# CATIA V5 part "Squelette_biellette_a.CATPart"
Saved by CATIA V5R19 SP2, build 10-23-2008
Part number: squelette_biellette_a
Bounding box of the stored display mesh (mm): x -23 to -23, y -294 to -294, z -144 to 80
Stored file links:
  G:\EU_thinkMotion\CFAO_2010\MMS_groupe3\MMS_groupe3\pmayet\pmayet_assemblage_animation\pmayet_assemblage_animation\Squelette_biellette_a.CATPart
  G:\EU_thinkMotion\CFAO_2010\MMS_groupe3\MMS_groupe3\pmayet\pmayet_assemblage_animation\pmayet_assemblage_animation\pmayet_assemblage_animation.CATProduct
  G:\EU_thinkMotion\CFAO_2010\MMS_groupe3\MMS_groupe3\pmayet\pmayet_assemblage_animation\pmayet_assemblage_animation\Biellette_b.CATPart
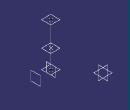
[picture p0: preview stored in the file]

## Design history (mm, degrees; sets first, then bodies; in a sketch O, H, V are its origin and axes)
Set1
  Point1 "Point.12_biellete_a": linked copy from another document
  Point2 "Point.15_biellete_a": linked copy from another document
  Point3 "Point.13_biellete_a": linked copy from another document
  Plane1: linked copy from another document
Set2
  Line1: type PtPt, FirstPoint Point1, SecondPoint Point2
  Plane2: type Normal, Curve Line1, RefPoint Point1
  Plane3: type Normal, Curve Line1, RefPoint Point2
  Plane4: type Normal, Curve Line1, RefPoint Point3
  Plane5: type OffsetPt, RefPlane Plane1, RefPoint Point2
Body1 (main body)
